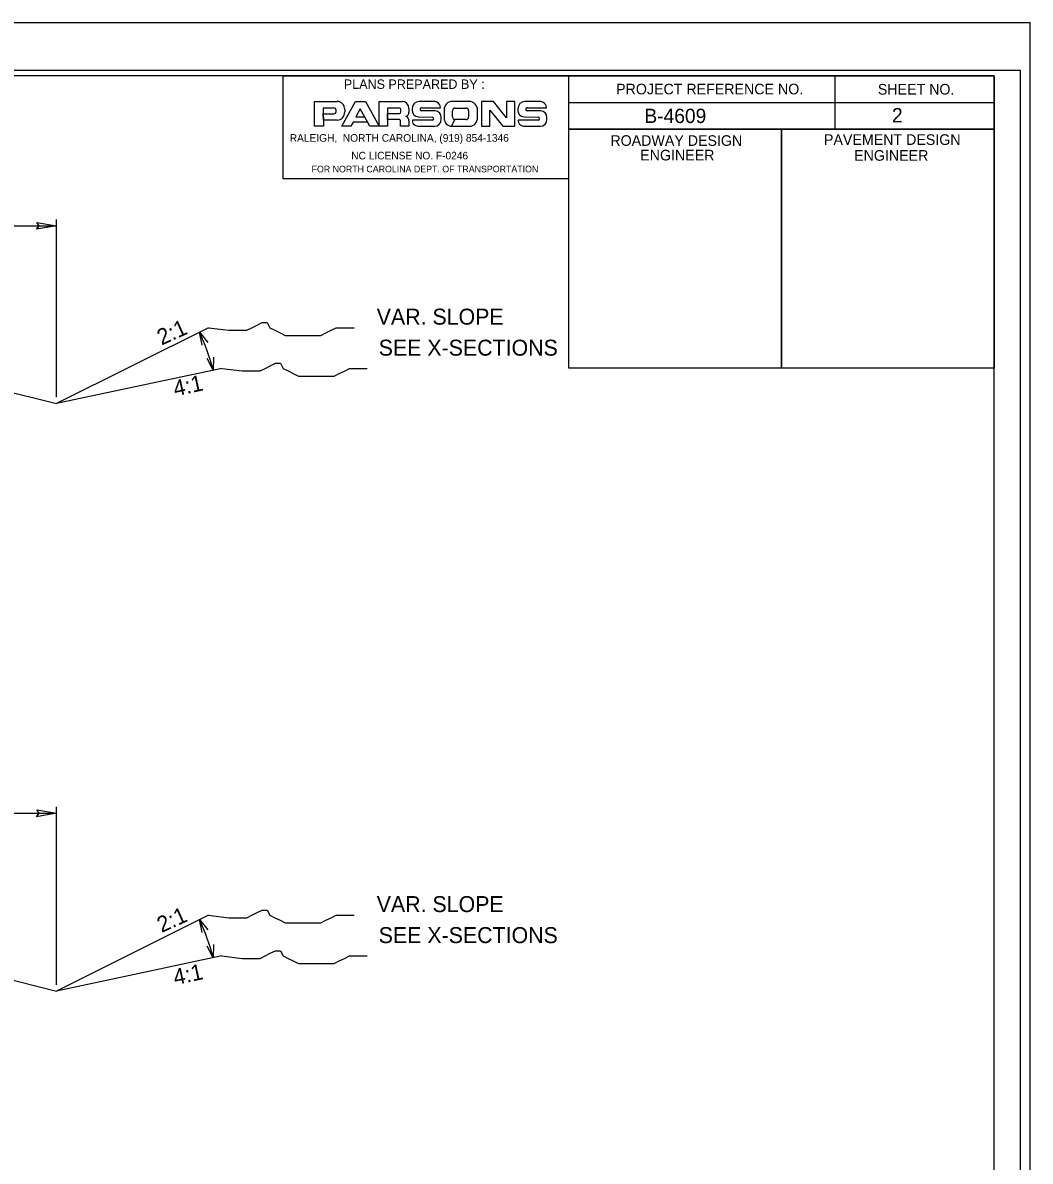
# Model space of a CAD drawing. Extents: x 573711 to 575883, y -54585 to -53485.
# Drawn here: x 574921 to 575395, y -54021 to -53485 of the extents above; entities that cross this region are included whole.
import ezdxf

# ---------------------------------------------------------------- set-up
doc = ezdxf.new("R2010")
doc.units = 0
for name, color, linetype in [('Old_Level_1', 7, 'Continuous'), ('Old_Level_11', 7, 'Continuous'), ('Old_Level_2', 7, 'Continuous'), ('Sheet Cutting Line CELL', 7, 'Continuous'), ('Sheet Data Field CELL', 7, 'Continuous'), ('Sheet Plot Border Inside CELL', 7, 'Continuous'), ('Sheet Plot Border Outside CELL', 7, 'Continuous'), ('Sheet Typical CELL', 7, 'Continuous'), ('Typical Terminator CELL', 7, 'Continuous')]:
    doc.layers.add(name, color=color, linetype=linetype)

msp = doc.modelspace()

# ---------------------------------------------------------------- linework, layer by layer
at = {"layer": 'Old_Level_1'}
for p, q in [((575008.47, -53628.57), (574936.99, -53664.3)), ((574862.87, -53645.76), (574936.99, -53664.3)), ((575014.71, -53647.73), (574936.99, -53664.3)), ((575008.47, -53905.09), (574936.99, -53940.82)), ((574862.87, -53922.28), (574936.99, -53940.82)), ((575014.71, -53924.26), (574936.99, -53940.82))]:
    msp.add_line(p, q, dxfattribs=at)
for points in [[(575008.47, -53628.57), (575018.08, -53629.77), (575020.48, -53629.77), (575024.09, -53629.77), (575026.5, -53629.77), (575028.9, -53628.57), (575031.3, -53627.37), (575033.71, -53626.16), (575036.11, -53626.16), (575037.32, -53628.57), (575039.72, -53629.77), (575042.12, -53630.98), (575044.53, -53632.17), (575046.93, -53632.17), (575049.33, -53632.17), (575051.74, -53632.17), (575054.14, -53632.18), (575056.54, -53632.18), (575058.94, -53632.18), (575061.35, -53632.18), (575063.75, -53630.98), (575066.15, -53629.77), (575068.56, -53628.58), (575072.17, -53628.58), (575074.57, -53628.58), (575076.97, -53628.58)], [(575014.71, -53647.73), (575024.32, -53648.93), (575026.72, -53648.93), (575030.33, -53648.93), (575032.74, -53648.93), (575035.14, -53647.74), (575037.54, -53646.53), (575039.95, -53645.32), (575042.35, -53645.32), (575043.56, -53647.74), (575045.96, -53648.93), (575048.36, -53650.14), (575050.77, -53651.34), (575053.17, -53651.34), (575055.57, -53651.34), (575057.98, -53651.34), (575060.38, -53651.34), (575062.78, -53651.34), (575065.19, -53651.34), (575067.59, -53651.34), (575069.99, -53650.14), (575072.4, -53648.94), (575074.8, -53647.74), (575078.41, -53647.74), (575080.81, -53647.74), (575083.21, -53647.74)], [(575008.47, -53905.09), (575018.08, -53906.29), (575020.48, -53906.29), (575024.09, -53906.29), (575026.5, -53906.29), (575028.9, -53905.09), (575031.3, -53903.89), (575033.71, -53902.68), (575036.11, -53902.68), (575037.32, -53905.1), (575039.72, -53906.29), (575042.12, -53907.5), (575044.53, -53908.7), (575046.93, -53908.7), (575049.33, -53908.7), (575051.74, -53908.7), (575054.14, -53908.7), (575056.54, -53908.7), (575058.94, -53908.7), (575061.35, -53908.7), (575063.75, -53907.5), (575066.15, -53906.29), (575068.56, -53905.1), (575072.17, -53905.1), (575074.57, -53905.1), (575076.97, -53905.1)], [(575014.71, -53924.26), (575024.32, -53925.45), (575026.72, -53925.45), (575030.33, -53925.45), (575032.74, -53925.46), (575035.14, -53924.26), (575037.54, -53923.05), (575039.95, -53921.85), (575042.35, -53921.85), (575043.56, -53924.26), (575045.96, -53925.46), (575048.36, -53926.66), (575050.77, -53927.86), (575053.17, -53927.86), (575055.57, -53927.86), (575057.98, -53927.86), (575060.38, -53927.86), (575062.78, -53927.86), (575065.19, -53927.86), (575067.59, -53927.86), (575069.99, -53926.66), (575072.4, -53925.46), (575074.8, -53924.26), (575078.41, -53924.26), (575080.81, -53924.26), (575083.21, -53924.26)]]:
    msp.add_lwpolyline(points, dxfattribs=at)
at = {"layer": 'Old_Level_11'}
for p, q in [((574936.99, -53661.3), (574937, -53577.57)), ((574862.88, -53580.56), (574937, -53580.57)), ((574862.88, -53857.09), (574937, -53857.09)), ((574936.99, -53937.82), (574937, -53854.09))]:
    msp.add_line(p, q, dxfattribs=at)
for points in [[(575005.48, -53636.72), (575004.31, -53630.65), (575008.2, -53635.46)], [(575010.76, -53642.41), (575010.69, -53648.59), (575007.84, -53643.1)], [(575005.48, -53913.24), (575004.31, -53907.17), (575008.2, -53911.98)], [(575010.76, -53918.93), (575010.69, -53925.11), (575007.84, -53919.62)]]:
    msp.add_lwpolyline(points, dxfattribs=at)
for centre in [(574904.49, -53676.57), (574904.49, -53953.09)]:
    msp.add_arc(centre, 109.83, 14.7586, 24.7027, dxfattribs=at)
at = {"layer": 'Old_Level_2'}
for p, q in [((575043.68, -53510.01), (575178.08, -53510.01)), ((575043.68, -53558.44), (575043.68, -53510.01)), ((575178.08, -53558.44), (575178.08, -53510.01)), ((575068.5, -53526.77), (575068.5, -53526.08)), ((575072.58, -53525.86), (575072.58, -53527)), ((575098.99, -53527), (575098.99, -53525.7)), ((575102.78, -53525.32), (575102.78, -53527.08)), ((575104.26, -53525.62), (575104.26, -53526.09)), ((575114.27, -53522.03), (575107.62, -53522.03)), ((575108.69, -53525.01), (575117.69, -53525.01)), ((575119.33, -53526.01), (575119.33, -53529.91)), ((575131.14, -53522.03), (575123.01, -53522.03)), ((575123.29, -53529.37), (575123.29, -53526.39)), ((575124.42, -53525.16), (575129.73, -53525.16)), ((575130.86, -53526.39), (575130.86, -53529.37)), ((575135.11, -53529.61), (575135.11, -53526.31)), ((575154.02, -53525.62), (575154.02, -53526.09)), ((575164.03, -53522.03), (575157.37, -53522.03)), ((575158.45, -53525.01), (575167.45, -53525.01)), ((575107.2, -53529.31), (575113.76, -53529.45)), ((575115.12, -53526.47), (575108.69, -53526.47)), ((575117.98, -53530.45), (575117.98, -53529.53)), ((575122.87, -53533.73), (575124.42, -53530.6)), ((575156.96, -53529.31), (575163.52, -53529.45)), ((575164.88, -53526.47), (575158.45, -53526.47)), ((575167.74, -53530.45), (575167.73, -53529.53)), ((575108.05, -53533.73), (575114.91, -53533.73)), ((575122.87, -53533.74), (575131.29, -53533.73)), ((575157.8, -53533.73), (575164.67, -53533.73)), ((575178.08, -53558.44), (575043.68, -53558.44))]:
    msp.add_line(p, q, dxfattribs=at)
for points in [[(575067.64, -53525.16), (575062.48, -53525.16), (575062.48, -53527.84), (575062.55, -53530.83), (575062.55, -53533.73), (575058.4, -53533.73), (575058.4, -53522.03), (575069, -53522.03)], [(575098.49, -53525.17), (575092.7, -53525.17), (575092.7, -53527.77), (575092.7, -53530.6), (575092.7, -53533.73), (575088.85, -53533.73), (575088.85, -53522.03), (575099.7, -53522.03)], [(575069, -53530.83), (575062.55, -53530.83), (575062.48, -53527.84), (575067.5, -53527.84)], [(575102.78, -53531.21), (575102.78, -53533.73), (575098.85, -53533.73), (575098.85, -53531.05), (575098.35, -53530.6), (575092.7, -53530.6), (575092.7, -53527.77), (575098.27, -53527.77)], [(575113.76, -53530.9), (575104.4, -53530.9), (575104.4, -53531.13)], [(575129.73, -53530.6), (575124.42, -53530.6), (575122.87, -53533.73), (575131.29, -53533.73)], [(575163.52, -53530.9), (575154.16, -53530.9), (575154.16, -53531.13)]]:
    msp.add_lwpolyline(points, dxfattribs=at)
for points in [[(575071.24, -53533.73), (575077.68, -53522.03), (575082.35, -53522.03), (575088.72, -53533.73), (575084.33, -53533.73), (575079.87, -53525.55), (575077.82, -53529.3), (575081.92, -53529.3), (575083.27, -53531.74), (575076.54, -53531.74), (575075.48, -53533.74)], [(575136.9, -53522.03), (575136.9, -53533.73), (575140.86, -53533.73), (575140.86, -53526.16), (575146.95, -53533.73), (575152.54, -53533.73), (575152.54, -53522.03), (575148.72, -53522.03), (575148.72, -53529.83), (575142.56, -53522.03)]]:
    msp.add_lwpolyline(points, close=True, dxfattribs=at)
for centre, major_axis, ratio, start_param, end_param in [((575067.64, -53526.09), (0, 0.918), 0.93676, 4.712389, 6.283185), ((575069, -53525.86), (0, 3.83), 0.93676, 4.712389, 6.283185), ((575098.49, -53525.7), (0, 0.536), 0.934072, 4.712389, 6.283185), ((575099.7, -53525.32), (0, 3.29), 0.934072, 4.712389, 6.283185), ((575107.62, -53525.63), (0, 3.6), 0.934072, 0, 1.570796), ((575107.26, -53526.09), (0, -3.21), 0.934072, 4.712389, 6.260753), ((575108.69, -53525.74), (0, 0.727), 0.934072, 0, 3.141593), ((575114.26, -53527), (0, 4.97), 0.934072, 5.902203, 6.283185), ((575114.98, -53525.09), (0, 2.91), 0.934072, 4.738699, 5.901866), ((575123.01, -53526.01), (0, 3.98), 0.924824, 0, 1.570796), ((575124.42, -53526.39), (0, -1.22), 0.924824, 3.141593, 4.712389), ((575129.73, -53526.39), (0, 1.22), 0.924824, 4.712389, 6.283185), ((575131.15, -53526.31), (0, 4.28), 0.924824, 4.712389, 6.283185), ((575157.38, -53525.63), (0, 3.6), 0.934072, 0, 1.570796), ((575157.02, -53526.09), (0, -3.21), 0.934072, 4.712389, 6.260753), ((575158.45, -53525.74), (0, 0.727), 0.934072, 0, 3.141593), ((575164.02, -53527), (0, 4.97), 0.934072, 5.902203, 6.283185), ((575164.74, -53525.09), (0, 2.91), 0.934072, 4.738699, 5.901866), ((575067.5, -53526.77), (0, 1.07), 0.93676, 3.141593, 4.712389), ((575069, -53527), (0, 3.83), 0.93676, 3.141593, 4.712389), ((575098.28, -53527), (0, 0.765), 0.934072, 3.141593, 4.712389), ((575100.92, -53527.08), (0, 1.99), 0.934072, 3.34512, 4.712389), ((575100.63, -53531.21), (0, 2.3), 0.934072, 4.712389, 5.969561), ((575106.62, -53531.13), (0, -2.37), 0.934072, 4.712389, 5.988639), ((575113.76, -53530.18), (0, 0.727), 0.934072, 3.141593, 6.283185), ((575114.91, -53530.45), (0, 3.29), 0.934072, 3.141593, 4.712389), ((575115.12, -53529.53), (0, 3.06), 0.934072, 4.712389, 6.283185), ((575122.87, -53529.91), (0, -3.83), 0.924824, 4.712389, 6.283185), ((575124.42, -53529.37), (0, -1.22), 0.924824, 4.712389, 6.283185), ((575129.73, -53529.37), (0, 1.22), 0.924824, 3.141593, 4.712389), ((575131.29, -53529.6), (0, 4.13), 0.924824, 3.141593, 4.712389), ((575156.38, -53531.13), (0, -2.37), 0.934072, 4.712389, 5.988639), ((575163.52, -53530.18), (0, 0.727), 0.934072, 3.141593, 6.283185), ((575164.67, -53530.45), (0, 3.29), 0.934072, 3.141593, 4.712389), ((575164.88, -53529.53), (0, 3.06), 0.934072, 4.712389, 6.283185), ((575108.05, -53526.09), (0, 7.65), 0.934072, 2.847261, 3.141593), ((575157.81, -53526.09), (0, 7.65), 0.934072, 2.847261, 3.141593)]:
    msp.add_ellipse(centre, major_axis=major_axis, ratio=ratio, start_param=start_param, end_param=end_param, dxfattribs=at)
at = {"layer": 'Sheet Cutting Line CELL'}
msp.add_line((575395.13, -53485.01), (573711.13, -53485.01), dxfattribs=at)
at = {"layer": 'Sheet Plot Border Inside CELL'}
msp.add_lwpolyline([(575390.63, -53507.46), (573724.13, -53507.46), (573724.13, -54562.56), (575390.63, -54562.56)], close=True, dxfattribs=at)
at = {"layer": 'Sheet Plot Border Outside CELL'}
msp.add_lwpolyline([(575395.13, -53485.01), (573711.13, -53485.01), (573711.13, -54585.01), (575395.13, -54585.01)], close=True, dxfattribs=at)
at = {"layer": 'Sheet Typical CELL'}
for p, q in [((575303.13, -53510.06), (575303.13, -53535.06)), ((575178.08, -53522.56), (575378.13, -53522.56)), ((575278.13, -53535.06), (575278.13, -53647.51))]:
    msp.add_line(p, q, dxfattribs=at)
for points in [[(575378.13, -53510.01), (573878.13, -53510.01), (573878.13, -54560.01), (575378.13, -54560.01)], [(575178.08, -53510.01), (575378.13, -53510.01), (575378.13, -53535.06), (575178.08, -53535.06)], [(575178.08, -53535.06), (575278.13, -53535.06), (575278.13, -53647.56), (575178.08, -53647.56)], [(575278.13, -53535.06), (575378.13, -53535.06), (575378.13, -53647.56), (575278.13, -53647.56)]]:
    msp.add_lwpolyline(points, close=True, dxfattribs=at)
at = {"layer": 'Typical Terminator CELL'}
for points in [[(574927.63, -53578.96), (574937, -53580.57), (574927.58, -53582.24), (574928.77, -53580.57)], [(574927.63, -53855.48), (574937, -53857.09), (574927.58, -53858.76), (574928.77, -53857.09)]]:
    msp.add_lwpolyline(points, close=True, dxfattribs=at)

# ---------------------------------------------------------------- texts
at = {"layer": 'Old_Level_1'}
for s, rotation, p in [('VAR. SLOPE', 359.9948, (575087.61, -53627.11)), ('2:1', 24.2085, (574986.39, -53636.97)), ('SEE X-SECTIONS', 359.9948, (575088.55, -53641.71)), ('4:1', 12.4568, (574992.8, -53660.97)), ('VAR. SLOPE', 359.9948, (575087.61, -53903.64)), ('2:1', 24.2085, (574986.39, -53913.49)), ('SEE X-SECTIONS', 359.9948, (575088.55, -53918.24)), ('4:1', 12.4568, (574992.8, -53938.12))]:
    msp.add_text(s, height=7.513, rotation=rotation, dxfattribs=at).set_placement(p)
at = {"layer": 'Old_Level_2'}
for s, height, rotation, p in [('PLANS PREPARED BY : ', 4.4145, 359.999, (575072.15, -53516.12)), ('RALEIGH,  NORTH CAROLINA, (919) 854-1346', 3.5754, 360, (575046.7, -53541.01)), ('NC LICENSE NO. F-0246', 3.5754, 360, (575075.64, -53549.33)), ('FOR NORTH CAROLINA DEPT. OF TRANSPORTATION', 3.1013, 359.9999, (575056.98, -53555.42))]:
    msp.add_text(s, height=height, rotation=rotation, dxfattribs=at).set_placement(p)
at = {"layer": 'Sheet Data Field CELL'}
for s, p in [('B-4609   ', (575213.59, -53532.21)), ('2  ', (575330.1, -53531.91))]:
    msp.add_text(s, height=6.75, dxfattribs=at).set_placement(p)
at = {"layer": 'Sheet Typical CELL'}
for s, height, p in [('PROJECT REFERENCE NO.', 5.0001, (575200.28, -53518.71)), ('SHEET NO.', 5, (575323.43, -53518.81)), ('ROADWAY DESIGN', 5.0001, (575197.58, -53542.96)), ('PAVEMENT DESIGN', 5.0001, (575298.08, -53542.51)), ('ENGINEER', 5, (575211.63, -53549.81)), ('ENGINEER', 5, (575312.28, -53549.96))]:
    msp.add_text(s, height=height, dxfattribs=at).set_placement(p)

doc.saveas('drawing.dxf')
